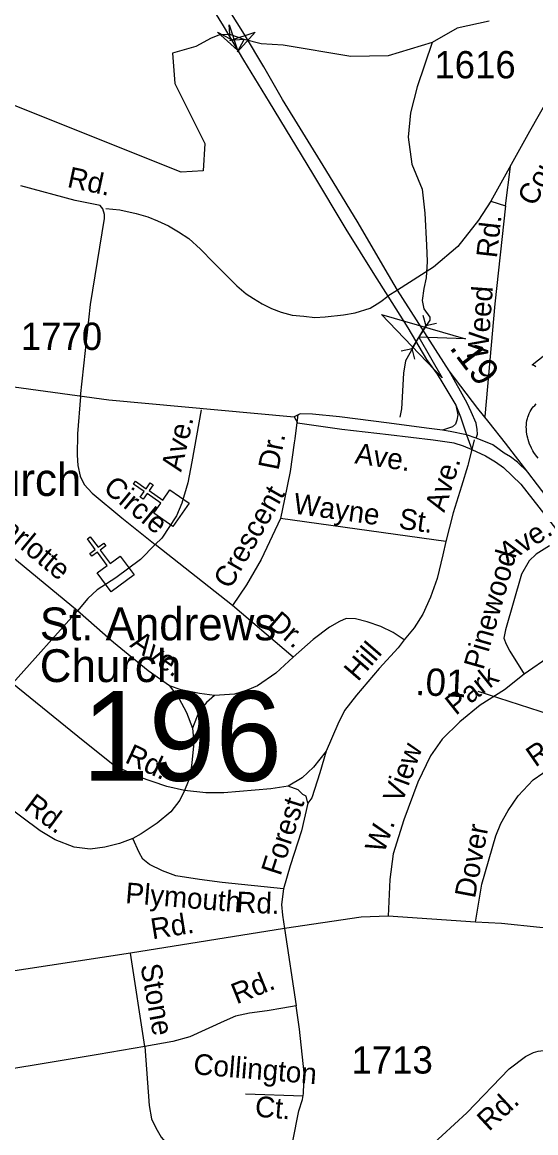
# Model space of a CAD drawing. Extents: x 2220236 to 2384410, y 720751 to 894131.
# Drawn here: x 2344734 to 2347083, y 803880 to 808960 of the extents above; entities that cross this region are included whole.
import ezdxf

# ---------------------------------------------------------------- set-up
doc = ezdxf.new("R2010")
doc.units = 0
doc.layers.add('Default', color=7, linetype='Continuous')

msp = doc.modelspace()

# ---------------------------------------------------------------- linework, layer by layer
at = {"layer": 'Default'}
for p, q in [((2346943.9, 808120.5), (2346966.2, 808300.2)), ((2346877.2, 808141), (2346943.9, 808120.5)), ((2346565.9, 807619.2), (2346579.3, 807570.3)), ((2346628.9, 807581), (2346579.3, 807570.3)), ((2346516.6, 807466.9), (2346579.3, 807570.3)), ((2346467, 807456.1), (2346516.6, 807466.9)), ((2346530, 807417.9), (2346516.6, 807466.9)), ((2345994.9, 807165.3), (2345980.1, 807053.3)), ((2346800, 807049.4), (2346773.5, 806937.6)), ((2344985.9, 806266.7), (2344436.6, 806720.1)), ((2346671.5, 806584.9), (2345914.5, 806689.8)), ((2345695.4, 806291.3), (2345342.1, 806571)), ((2344985.9, 806266.7), (2344689.9, 805935.3)), ((2345972.2, 806054.7), (2345695.4, 806291.3)), ((2347153.6, 806062.9), (2347028.8, 805977.4)), ((2347973.4, 805524.9), (2346818.6, 805898)), ((2346806.2, 804843.8), (2346407.7, 804871.2)), ((2345933.9, 804814.7), (2345229.3, 804702)), ((2345933.9, 804814.7), (2345986.1, 804460)), ((2345229.3, 804702), (2344521.6, 804593.5)), ((2345294.2, 804275.1), (2345229.3, 804702)), ((2346018.4, 804047.8), (2345754.4, 804056.9))]:
    msp.add_line(p, q, dxfattribs=at)
for points in [[(2345480.9, 809244.3), (2345496.4, 809215.6), (2345585.8, 809051.3), (2345652.8, 808942.6)], [(2345749.9, 808902.8), (2345658, 809050.6), (2345596.2, 809160.4)], [(2346869.5, 808964.1), (2346722.8, 808932.1), (2346608.7, 808866.5), (2346407.1, 808805.7), (2346237.1, 808803.3), (2345927.2, 808855), (2345827, 808861.1), (2345748.1, 808881.1), (2345688, 808901.8), (2345641.2, 808903.6), (2345598.1, 808887.2), (2345527.1, 808848.3), (2345421.5, 808817.9), (2345431.5, 808679), (2345568.4, 808405.6), (2345561.5, 808280.5), (2345461.4, 808273.2), (2344448.4, 808678.2)], [(2345652.8, 808942.6), (2345746.4, 808785.4), (2345862.5, 808594.2), (2346061, 808267.1), (2346213.6, 808013.2), (2346345.3, 807802.6), (2346406.1, 807706.8)], [(2346450.2, 807734.3), (2346393.5, 807829.9), (2346269.8, 808042.1), (2346122, 808284.8), (2345923.4, 808605.5), (2345838.6, 808755), (2345749.9, 808902.8)], [(2346608.7, 808866.5), (2346540.7, 808664.8), (2346509.1, 808545.7), (2346499.4, 808433.9), (2346516.4, 808310), (2346562.5, 808195.8), (2346574.7, 808086.5), (2346583.2, 807940.2), (2346585.6, 807864.8), (2346580.7, 807790.7), (2346571, 807740.9), (2346562.5, 807686.2), (2346571, 807648.6), (2346597.7, 807610.9), (2346597.7, 807597.5), (2346583.2, 807573.2), (2346547.9, 807518.6), (2346487.2, 807410.4), (2346477.5, 807354.2), (2346467.8, 807191.4), (2346460.5, 807152.7)], [(2347268.3, 808837.9), (2347053.4, 808459.4), (2346877.2, 808141), (2346820.8, 808053.7), (2346725.3, 807933.2), (2346615.5, 807839.8), (2346450.2, 807734.3)], [(2345000.3, 807248.4), (2345046.2, 807667.8), (2345110.4, 808061.8), (2345110, 808079.6), (2345101.8, 808105.6), (2345089.5, 808121.3), (2344975.2, 808144.5), (2344727.2, 808211.2)], [(2345116.3, 808107.7), (2345179.6, 808100.8), (2345254.9, 808085.4), (2345307.9, 808070), (2345352.4, 808051.2), (2345402, 808028.9), (2345448.2, 808001.5), (2345496.1, 807970.7), (2345549.1, 807921.1), (2345608.9, 807861.2), (2345679.1, 807791), (2345715, 807753.4), (2345757.7, 807717.4), (2345792, 807695.2), (2345831.3, 807671.2), (2345874.1, 807650.7), (2345918.5, 807633.6), (2345968.1, 807619.9), (2346021.2, 807614.7), (2346072.5, 807609.6), (2346118.6, 807611.3), (2346202.5, 807621.6), (2346257.2, 807630.1), (2346325.6, 807652.4), (2346356.4, 807671.1)], [(2346943.9, 808120.5), (2346894.9, 807670.8), (2346849, 807156.7)], [(2346450.2, 807734.3), (2346406.1, 807706.8)], [(2346686.2, 807364.9), (2346450.2, 807734.3)], [(2346356.4, 807671.1), (2346373.5, 807681.5), (2346406.1, 807706.8)], [(2346406.1, 807706.8), (2346497.2, 807562.4), (2346583.2, 807416.9), (2346631.8, 807350.1), (2346653.4, 807314.2), (2346716.5, 807208.1), (2346738.2, 807154.8), (2346766.4, 807072.4)], [(2340486.7, 807629.8), (2342745, 807523.7), (2342907, 807512.4), (2343149.5, 807491.1), (2343404.6, 807462.1), (2343714.1, 807426.7), (2345129.8, 807232.1), (2345977.7, 807154.8)], [(2347083.4, 807383.3), (2347076.9, 807387.2), (2347070.6, 807390.3), (2347066.6, 807391.9), (2347195.2, 807494.4)], [(2347046, 806901.9), (2346944.1, 807034.9), (2346869.4, 807128.4), (2346817.1, 807193.3), (2346686.2, 807364.9)], [(2346810.2, 807057.1), (2346816.1, 807075.6), (2346814.5, 807097.2), (2346809.2, 807125.2), (2346787, 807177), (2346769.1, 807217.6), (2346686.2, 807364.9)], [(2345000.3, 807248.4), (2344986.3, 807076.5), (2344985.3, 806978.6), (2344988, 806932.5), (2344998.6, 806882.7), (2345017, 806845), (2345053.4, 806805.3), (2345188.8, 806693), (2345342.1, 806571)], [(2345552.6, 807186.8), (2345509.5, 806948.8), (2345490.6, 806852.6), (2345463.8, 806760.4), (2345438.6, 806702), (2345371.7, 806599.2), (2345342.1, 806571)], [(2346716.5, 807208.1), (2346725.5, 807163.8), (2346721.3, 807138.9), (2346715.5, 807121.5), (2346702.3, 807109.4), (2346655.8, 807093.5)], [(2347092.9, 806965.7), (2347081.6, 806980.3), (2347074.4, 806990.9), (2347069.8, 806998.6), (2347062.9, 807011.1), (2347059.2, 807018.9), (2347054.3, 807030.3), (2347050.5, 807040.7), (2347047.3, 807050.6), (2347045.6, 807056.9), (2347043.1, 807067.9), (2347041.7, 807075.7), (2347040.2, 807086.5), (2347039.4, 807097.8), (2347039.3, 807108.2), (2347039.5, 807116.9), (2347040.5, 807127), (2347042.2, 807137.7), (2347044.3, 807146.9), (2347046.1, 807153.5), (2347048.9, 807161.5), (2347052.5, 807170.4), (2347056.7, 807178.9), (2347060.8, 807186), (2347065.9, 807193.6), (2347070.9, 807200.1), (2347077.5, 807207.2), (2347084.3, 807213.7)], [(2346766.4, 807072.4), (2346691.7, 807088.3), (2346655.8, 807093.5), (2346583.5, 807102.5), (2346412.4, 807126.3), (2346185.2, 807154.2), (2346061.6, 807166.9), (2346004.6, 807169), (2345977.7, 807154.8)], [(2345977.7, 807154.8), (2345993, 807127.3), (2346195.5, 807097.8), (2346408.5, 807073.3), (2346613, 807050), (2346697.9, 807037.9), (2346707.5, 807036.5), (2346750.9, 807022.5), (2346789.7, 807005.9)], [(2346766.4, 807072.4), (2346789.7, 807005.9)], [(2347046, 806901.9), (2346998.6, 806946.6), (2346966.5, 806971.5), (2346938, 806988.5), (2346885.7, 807026), (2346830.3, 807049.7), (2346810.2, 807057.1), (2346766.4, 807072.4)], [(2345980.1, 807053.3), (2345977.6, 807035.3), (2345958.7, 806905.2), (2345933.5, 806778), (2345914.5, 806689.8)], [(2346789.7, 807005.9), (2346852.6, 806975.9), (2346898.8, 806948.2), (2346934.3, 806923), (2347014.4, 806847.4), (2347298.8, 806482.4), (2347357.3, 806415), (2347516, 806189.4), (2347627.8, 806041), (2347745.7, 805894.2), (2347764.5, 805869.5)], [(2346773.5, 806937.6), (2346772.4, 806932.6), (2346742.4, 806837.7), (2346704, 806715.2), (2346671.5, 806584.9)], [(2348097.3, 805531.4), (2347898, 805797.6), (2347827.8, 805891.8), (2347689.5, 806075.3), (2347566.8, 806231.4), (2347503.4, 806312.7), (2347415.8, 806431), (2347165, 806746.7), (2347090.6, 806843.8), (2347046, 806901.9)], [(2345914.5, 806689.8), (2345826.9, 806502.8), (2345760.2, 806386), (2345695.4, 806291.3)], [(2345342.1, 806571), (2345275, 806502.2), (2345162, 806418.8), (2345076.8, 806363.9), (2345033.2, 806323.3), (2344985.9, 806266.7)], [(2346671.5, 806584.9), (2346658.2, 806522.9), (2346631.6, 806414.6), (2346600.6, 806330.3), (2346565.6, 806251.8), (2346526.3, 806189.4), (2346481, 806134.9)], [(2347145.4, 806565.1), (2347084.1, 806525.9), (2347052.5, 806495.6), (2347017.3, 806435.1), (2346944.3, 806180.4), (2346936.8, 806142.3), (2346947.2, 806114.5), (2346963.5, 806082.6), (2347028.8, 805977.4)], [(2345407.9, 805924), (2345309, 805992.8), (2345151.7, 806122.8), (2344985.9, 806266.7)], [(2346481, 806134.9), (2346430.6, 806168.3), (2346374.2, 806195.6), (2346312.1, 806216.8), (2346258, 806230), (2346215.9, 806231.5), (2346184.2, 806219.2), (2346138.4, 806192.7), (2346065.1, 806135.7), (2345972.2, 806054.7)], [(2346481, 806134.9), (2346453.4, 806098.6), (2346366.7, 806003.6), (2346262.2, 805882.3), (2346207, 805811.6), (2346177.7, 805749.4), (2346123.2, 805624.7)], [(2345972.2, 806054.7), (2345893.1, 805981.8), (2345809.8, 805924.8), (2345762.1, 805904.3), (2345704.2, 805885.5), (2345612.4, 805880.5)], [(2347028.8, 805977.4), (2346939.7, 805906.3), (2346828.5, 805835.2), (2346735.4, 805759.9), (2346654.3, 805681), (2346601.4, 805604.4), (2346542.7, 805483.7), (2346479, 805311.1), (2346430, 805155.3), (2346414.6, 805038.9), (2346407.7, 804871.2)], [(2345475.7, 805445), (2345395.5, 805463.9), (2345265, 805508.4), (2345156.3, 805559), (2345012.9, 805673.4), (2344689.9, 805935.3)], [(2345612.4, 805880.5), (2345544.4, 805889.6), (2345460, 805906.5), (2345407.9, 805924)], [(2345407.9, 805924), (2345450.6, 805868.5), (2345485.3, 805802.9), (2345512.2, 805731.4)], [(2345612.4, 805880.5), (2345576.7, 805848.1), (2345541.4, 805805.6), (2345512.2, 805731.4)], [(2345512.2, 805731.4), (2345519, 805663.4), (2345510, 805573.2), (2345502.7, 805523.3), (2345493.2, 805487.1), (2345475.7, 805445)], [(2346806.2, 804843.8), (2346835.3, 805016.7), (2346899.7, 805238.2), (2346923, 805294.4), (2346956.2, 805354.8), (2347001.5, 805421.2), (2347070.5, 805494.1), (2347203.5, 805585.8), (2347391.6, 805725.9)], [(2346123.2, 805624.7), (2346066.2, 805551.9), (2346014.7, 805503.4), (2345949.3, 805464.7)], [(2346123.2, 805624.7), (2346094.4, 805526.5), (2346057.9, 805411.9), (2346040, 805387.8)], [(2345240.3, 805226.3), (2345178.6, 805203.6), (2345110.9, 805186.6), (2345045, 805177.9), (2344971, 805186.9), (2344884.6, 805220), (2344816.1, 805261), (2344654.7, 805381.1), (2344404.4, 805582.1)], [(2345475.7, 805445), (2345454.3, 805400.7), (2345412.8, 805348.2), (2345351.5, 805295.5), (2345278.1, 805246.6), (2345240.3, 805226.3)], [(2345949.3, 805464.7), (2345871.5, 805453.7), (2345655.7, 805435.1), (2345573.7, 805434.2), (2345475.7, 805445)], [(2346040, 805387.8), (2346031.7, 805419.7), (2346017.6, 805427.5), (2345995.3, 805449.2), (2345949.3, 805464.7)], [(2346040, 805387.8), (2346011.6, 805261.4), (2345959.7, 805101), (2345929, 804996.5)], [(2345929, 804996.5), (2345648.7, 805025.3), (2345544.5, 805038), (2345436.4, 805054.6), (2345376, 805078), (2345315.8, 805107.1), (2345285.4, 805130.7), (2345269.1, 805162.6), (2345240.3, 805226.3)], [(2345929, 804996.5), (2345920.2, 804924.2), (2345923.7, 804874.6), (2345933.9, 804814.7)], [(2346407.7, 804871.2), (2346284.6, 804866), (2345933.9, 804814.7)], [(2347219.5, 804215.2), (2347276.2, 804316.1), (2347321.4, 804396), (2347378.1, 804491.6), (2347415.9, 804560.9), (2347429.8, 804610.8), (2347433.7, 804681.8), (2347424.3, 804717.5), (2347406.4, 804745.9), (2347394.9, 804765.8), (2347381.1, 804778.1), (2347340.9, 804797.6), (2347288.7, 804806.9), (2347100.7, 804818.6), (2346925.1, 804837.8), (2346806.2, 804843.8)], [(2345986.1, 804460), (2345925.2, 804450.2), (2345854.4, 804438.4), (2345773.8, 804426.6), (2345709, 804412.8), (2345657.8, 804391.2), (2345499.6, 804319.4), (2345422.9, 804297.7), (2345294.2, 804275.1)], [(2346020, 804060), (2346023, 804154), (2346001.9, 804353.8), (2345986.1, 804460)], [(2345294.2, 804275.1), (2345081.8, 804237.7), (2344429.2, 804129.5)], [(2345294.2, 804275.1), (2345314.9, 804005.4), (2345325.6, 803943.6), (2345344.2, 803902), (2345368.7, 803860.2), (2345393.1, 803830.5), (2345421.9, 803797.1), (2345475, 803767.6), (2345659.8, 803692.8), (2345765.1, 803643), (2345819.4, 803625.7), (2345861.4, 803622.2), (2345913.3, 803628.9)], [(2345461.4, 803059.4), (2345555.9, 803137.4), (2345679.1, 803223), (2345853.5, 803353.1), (2345934.8, 803393.3), (2345940.3, 803396.2), (2346148.6, 803487.4), (2346346.1, 803608.1), (2346484.7, 803712.5), (2346767.8, 803971.8), (2346960.1, 804172.2), (2347035.4, 804229.4), (2347072, 804246.8), (2347093.5, 804253.5), (2347130.1, 804257.9), (2347170.1, 804252.4), (2347210, 804241.3), (2347293.3, 804194.6)], [(2345913.3, 803628.9), (2345920.3, 803676.1), (2345930.1, 803723.3), (2345971.4, 803841.3), (2345999.1, 803979.7), (2346016.3, 804031.9), (2346020, 804060)]]:
    msp.add_lwpolyline(points, dxfattribs=at)
for points in [[(2345680.2, 808948.4), (2345718.3, 808832.5), (2345627.4, 808913.8), (2345684.9, 808883.5)], [(2345683.3, 808876.3), (2345799, 808914.6), (2345718, 808823.5), (2345748.1, 808881.1)], [(2346653.9, 807333.6), (2346376.8, 807622), (2346761, 807510.8), (2346547.9, 807518.6)], [(2345335.2, 806713.6), (2345367.4, 806760.5), (2345304.8, 806803.8), (2345286.6, 806777.5), (2345273.5, 806786.6), (2345291.7, 806812.9), (2345242.2, 806847.1), (2345251.3, 806860.3), (2345300.8, 806826.1), (2345319, 806852.4), (2345332.1, 806843.3), (2345313.9, 806817), (2345376.6, 806773.7), (2345409.4, 806821.1), (2345497, 806760.5), (2345422.7, 806653.1)], [(2345076.9, 806440.4), (2345122.6, 806474.3), (2345077.4, 806535.6), (2345051.7, 806516.6), (2345042.2, 806529.4), (2345067.9, 806548.4), (2345032.2, 806596.8), (2345045.1, 806606.3), (2345080.8, 806557.9), (2345106.6, 806576.9), (2345116, 806564.1), (2345090.3, 806545.1), (2345135.5, 806483.8), (2345182, 806518), (2345245.2, 806432.3), (2345140.1, 806354.7)]]:
    msp.add_lwpolyline(points, close=True, dxfattribs=at)

# ---------------------------------------------------------------- texts
for s, height, p in [('1616', 125, (2346618.9, 808702.8)), ('1770', 125, (2344727.4, 807460.5)), ('United Church', 150, (2343721.6, 806792.7)), ('St. Andrews', 150, (2344814.2, 806132.6)), ('Church', 150, (2344814.2, 805941.5)), ('196', 410.1, (2345007.4, 805489.8)), ('1713', 125, (2346239.9, 804150.9))]:
    msp.add_text(s, height=height, dxfattribs=at).set_placement(p)
for s, height, rotation, p in [('Country', 95, 60.8259, (2347076, 808112.9)), ('Rd.', 95, 347.8751, (2344935.5, 808206.6)), ('Rd.', 95, 83.5502, (2346904.2, 807878.2)), ('Weed', 95, 85.8283, (2346862.7, 807418.8)), ('.19', 125, 307.3464, (2346684.3, 807470.4)), ('Ave.', 95, 77.0139, (2345460.8, 806900.2)), ('Dr.', 95, 78.8492, (2345905.3, 806906.7)), ('Ave.', 95, 351.611, (2346251.5, 806942.6)), ('Ave.', 95, 72.5958, (2346663.9, 806714.5)), ('Circle', 95, 320.328, (2345099, 806820)), ('Crescent', 95, 60.2714, (2345685.3, 806362.4)), ('Charlotte', 95, 320.4634, (2344507.3, 806729.6)), ('Wayne', 95, 352.1105, (2345970.1, 806712.9)), ('St.', 95, 352.1105, (2346452.2, 806644)), ('Ave.', 95, 32.6388, (2346952.5, 806482.9)), ('Pinewood', 95, 74.0066, (2346842.6, 805993.2)), ('Dr.', 95, 319.4772, (2345851.9, 806200.7)), ('Ave.', 95, 325.1752, (2345222.1, 806105.7)), ('Hill', 95, 49.2545, (2346268.9, 805940.3)), ('.01', 125, 357.3367, (2346529.9, 805882.6)), ('Park', 95, 38.5885, (2346716.4, 805786.1)), ('Rd.', 95, 34.5863, (2347080.5, 805549.8)), ('Rd.', 95, 335.0379, (2345198.6, 805575.5)), ('View', 95, 69.7424, (2346470.2, 805381.9)), ('Rd.', 95, 323.3463, (2344736, 805361.5)), ('Forest', 95, 72.0703, (2345914.7, 805051.3)), ('W.', 95, 70.4216, (2346388.4, 805154.3)), ('Dover', 95, 79.3195, (2346804.1, 804949.1)), ('Plymouth', 95, 355.3566, (2345203.2, 804930.8)), ('Rd.', 95, 357.712, (2345711.7, 804888.6)), ('Rd.', 95, 9.0501, (2345329.2, 804764.5)), ('Stone', 95, 280.1717, (2345274, 804645.3)), ('Rd.', 95, 21.946, (2345713.9, 804467)), ('Collington', 95, 355.3362, (2345514.1, 804148)), ('Ct.', 95, 355.3362, (2345795.7, 803954.3)), ('Rd.', 95, 42.7525, (2346868, 803883.4))]:
    msp.add_text(s, height=height, rotation=rotation, dxfattribs=at).set_placement(p)

doc.saveas('drawing.dxf')
